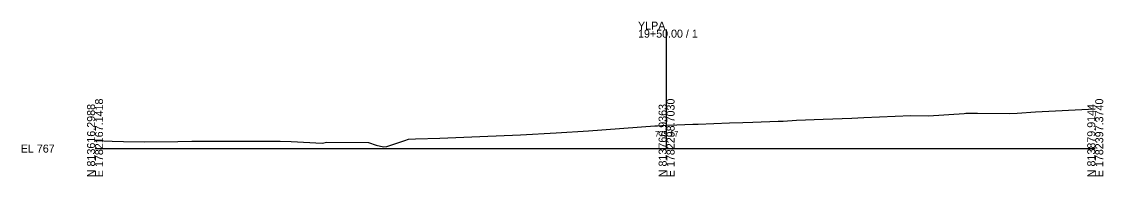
# Model space of a CAD drawing. Extents: x -76 to 1303, y -10 to 9544.
# Drawn here: x -75.7 to 302.8, y 9490.3 to 9544.4 of the extents above; entities that cross this region are included whole.
import ezdxf

# ---------------------------------------------------------------- set-up
doc = ezdxf.new("R2010")
doc.units = 0
for name, color, linetype in [('Exist Cross Section Cell', 7, 'Continuous'), ('Exist XS Center Line Elevation Label', 7, 'Continuous'), ('Exist XS Ground Line', 7, 'Continuous')]:
    doc.layers.add(name, color=color, linetype=linetype)

msp = doc.modelspace()

# ---------------------------------------------------------------- linework, layer by layer
at = {"layer": 'Exist Cross Section Cell'}
for p, q in [((150, 9500), (150, 9541.58)), ((-50, 9500), (150, 9500)), ((150, 9500), (300, 9500))]:
    msp.add_line(p, q, dxfattribs=at)
at = {"layer": 'Exist XS Ground Line'}
for p, q in [((272.62, 9512.43), (279.04, 9512.91)), ((279.04, 9512.91), (300, 9513.86)), ((161.06, 9508.55), (171.96, 9509.02)), ((171.96, 9509.02), (176.64, 9509.09)), ((176.64, 9509.09), (180.17, 9509.24)), ((180.17, 9509.24), (189.08, 9509.58)), ((189.08, 9509.58), (190.82, 9509.64)), ((190.82, 9509.64), (195.41, 9509.94)), ((195.41, 9509.94), (204.83, 9510.24)), ((204.83, 9510.24), (214.8, 9510.61)), ((214.8, 9510.61), (219.04, 9510.85)), ((219.04, 9510.85), (235.49, 9511.52)), ((235.49, 9511.52), (241.66, 9511.5)), ((241.66, 9511.5), (254.17, 9512.33)), ((254.17, 9512.33), (254.68, 9512.35)), ((254.68, 9512.35), (258.8, 9512.34)), ((258.8, 9512.34), (270.16, 9512.28)), ((270.16, 9512.28), (272.62, 9512.43)), ((98.9, 9504.79), (111.31, 9505.49)), ((111.31, 9505.49), (122.62, 9506.18)), ((122.62, 9506.18), (145.94, 9507.91)), ((145.94, 9507.91), (146.79, 9507.99)), ((146.79, 9507.99), (148.34, 9508.12)), ((148.34, 9508.12), (150, 9508.17)), ((150, 9508.17), (153.63, 9508.27)), ((153.63, 9508.27), (159.2, 9508.49)), ((159.2, 9508.49), (161.06, 9508.55)), ((-50, 9502.81), (-43.98, 9502.56)), ((-43.98, 9502.56), (-40.07, 9502.46)), ((-40.07, 9502.46), (-32.68, 9502.34)), ((-32.68, 9502.34), (-20.99, 9502.49)), ((-20.99, 9502.49), (-16.13, 9502.57)), ((-16.13, 9502.57), (0.02, 9502.62)), ((0.02, 9502.62), (1.72, 9502.66)), ((1.72, 9502.66), (2.76, 9502.59)), ((2.76, 9502.59), (12.44, 9502.56)), ((12.44, 9502.56), (14.75, 9502.63)), ((14.75, 9502.63), (18.66, 9502.54)), ((18.66, 9502.54), (29.52, 9501.94)), ((29.52, 9501.94), (31.15, 9502.22)), ((31.15, 9502.22), (45.7, 9502.16)), ((45.7, 9502.16), (48.32, 9501.19)), ((48.32, 9501.19), (50.88, 9500.67)), ((52.08, 9500.72), (58.45, 9502.82)), ((58.45, 9502.82), (59.7, 9503.3)), ((59.7, 9503.3), (62.13, 9503.4)), ((62.13, 9503.4), (70.62, 9503.63)), ((70.62, 9503.63), (84.69, 9504.26)), ((84.69, 9504.26), (98.9, 9504.79)), ((50.88, 9500.67), (52.08, 9500.72))]:
    msp.add_line(p, q, dxfattribs=at)

# ---------------------------------------------------------------- texts
at = {"layer": 'Exist Cross Section Cell'}
for s, p in [('YLPA', (140, 9541.58)), ('19+50.00 / 1', (140, 9538.78)), ('EL 767', (-76, 9498.6))]:
    msp.add_text(s, height=2.8, dxfattribs=at).set_placement(p)
for s, p in [('E 1782167.1418', (-47.2, 9490)), ('E 1782298.7030', (152.8, 9490)), ('E 1782397.3740', (302.8, 9490)), ('N 813616.2988', (-50, 9490)), ('N 813766.9363', (150, 9490)), ('N 813879.9144', (300, 9490))]:
    msp.add_text(s, height=2.8, rotation=90, dxfattribs=at).set_placement(p)
at = {"layer": 'Exist XS Center Line Elevation Label'}
msp.add_text('775.17', height=2, dxfattribs=at).set_placement((145.94, 9504.17))

doc.saveas('drawing.dxf')
